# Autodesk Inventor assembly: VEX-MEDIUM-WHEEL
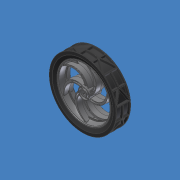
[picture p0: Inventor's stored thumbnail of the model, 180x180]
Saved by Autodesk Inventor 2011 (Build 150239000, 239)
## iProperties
Created: 2007-08
Part Number: VEX-MEDIUM-WHEEL
Document SubType Name: Assembly
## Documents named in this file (3)
- C:\Data Folder\VEX 2011\Inventor Datasets\Unit 16\Components\VEX-MEDIUM-WHEEL.iam
- C:\Data Folder\VEX 2011\Inventor Datasets\Unit 16\Components\MEDIUM-WHEEL-HUB.ipt
- C:\Data Folder\VEX 2011\Inventor Datasets\Unit 16\Components\MEDIUM-WHEEL-TIRE.ipt
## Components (2 placed, 2 different names)
1. MEDIUM-WHEEL-HUB
2. MEDIUM-WHEEL-TIRE
